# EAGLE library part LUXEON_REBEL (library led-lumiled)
LUXEON Rebel Display layer 93, Pins, and connect all contact points with a net. The thermal pads are defined in a separate gate with addlevel REQUEST. Draw a net named 'TH' and connect all thermal pads with it. Please read the Package's Description about DRC settings. Source: http://www.lumileds.com/pdfs/AB32.pdf
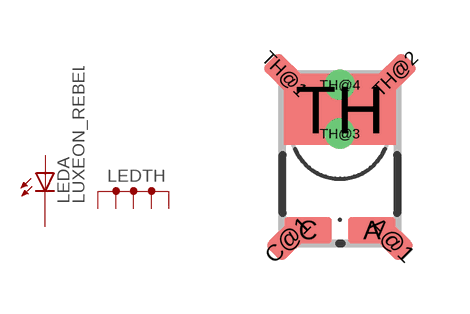
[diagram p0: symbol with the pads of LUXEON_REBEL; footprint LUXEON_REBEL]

Designator prefix LED; gates A=LED-A2C2 TH=LUXEON_THERMAL5

## LUXEON_REBEL (OC_FARNELL: unknown; OC_NEWARK: unknown)  [LUXEON_REBEL]
A  A:A  pas
A@1  A:A  pas
C  A:C  pas
C@1  A:C  pas
TH  TH:TH  pwr
TH@1  TH:TH  pwr
TH@2  TH:TH  pwr
TH@3  TH:TH  pwr
TH@4  TH:TH  pwr

## Footprint LUXEON_REBEL (pad centres in mm)
LUXEON® Rebel LED Set DRC - Clearance - Same Signals to 0 to avoid DRC error message for Pad in SMD. Please read the Device's Description how to connect it correctly in the Schematic. Source: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
smd 1.2 x 0.67: A 0.8,-2.51; C -0.8,-2.51
smd 1 x 0.6 rotated 315: A@1 1.31,-2.75
smd 1 x 0.6 rotated 225: C@1 -1.31,-2.75
smd 2.8 x 1.77: TH 0,0.51
smd 1 x 0.6 rotated 135: TH@1 -1.39,1.39
smd 1 x 0.6 rotated 45: TH@2 1.39,1.39
drill 0.25 pad 0.4 round: TH@3 0,-0.095; TH@4 0,1.125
